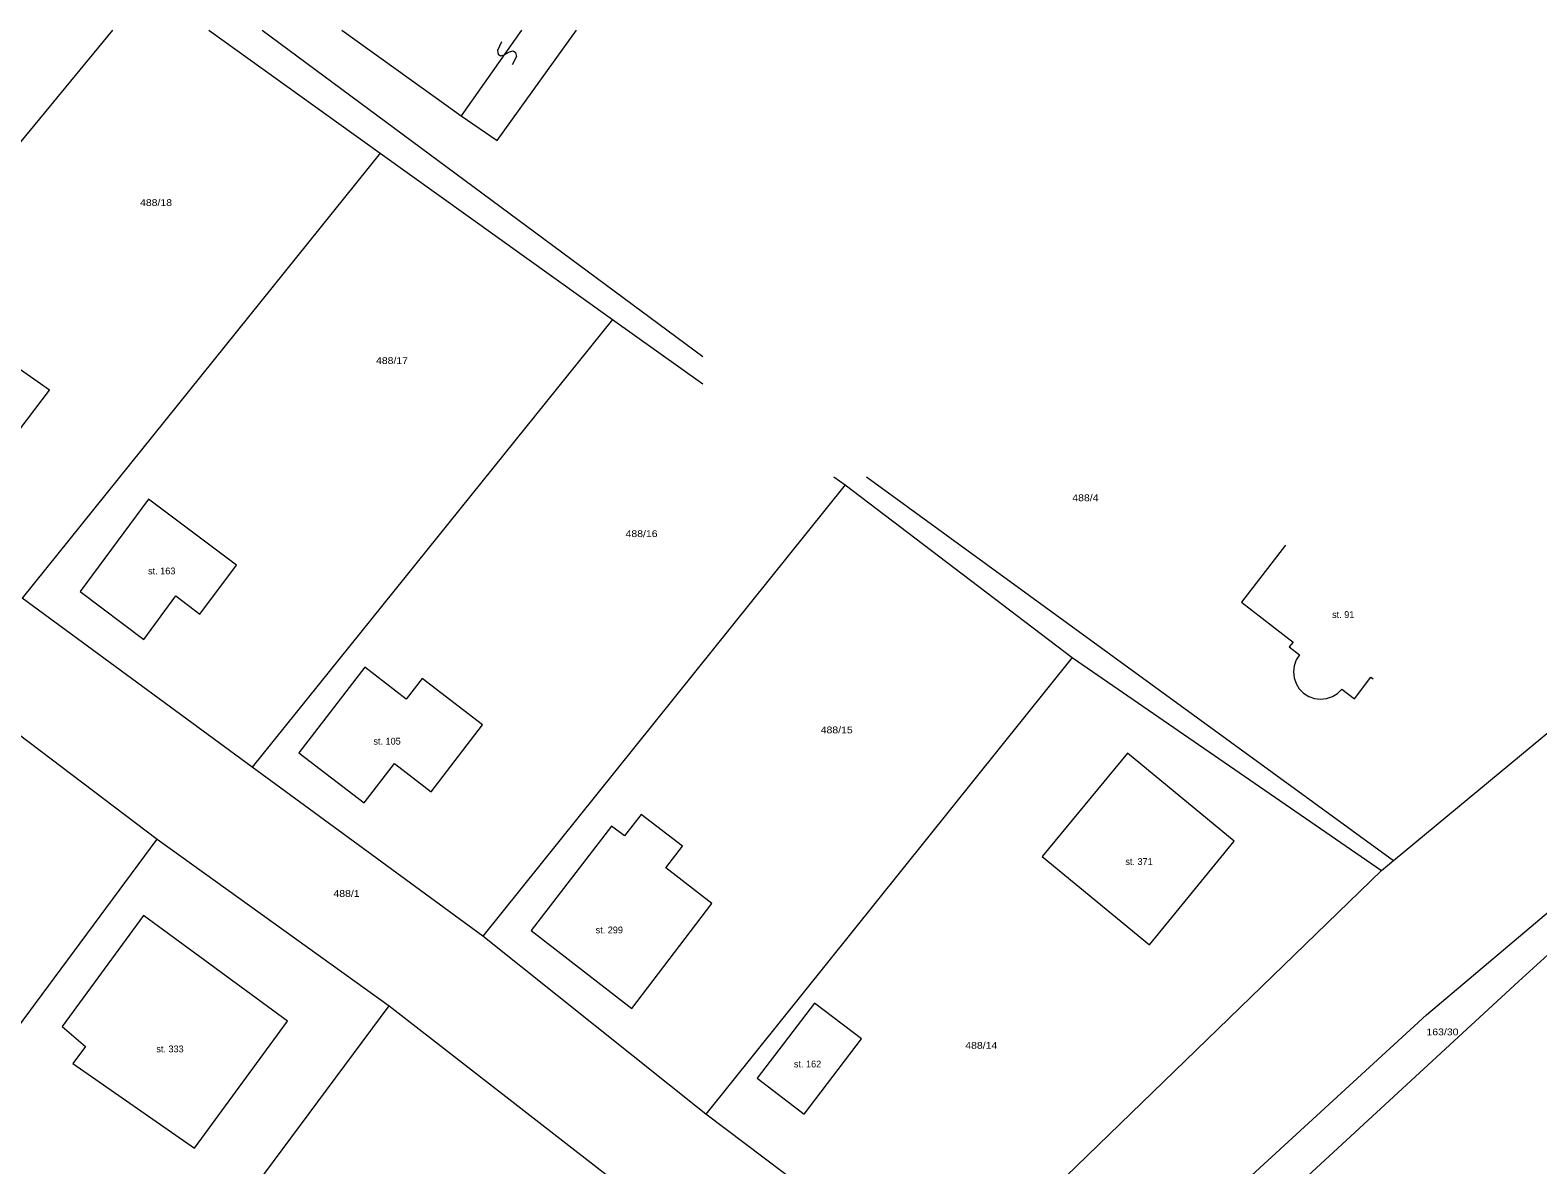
# Model space of a CAD drawing. Extents: x -694702 to -694000, y -1089746 to -1089192.
# Drawn here: x -694548.9 to -694438, y -1089489.2 to -1089405.7 of the extents above; entities that cross this region are included whole.
import ezdxf

# ---------------------------------------------------------------- set-up
doc = ezdxf.new("R2010")
doc.units = 0
doc.header["$LTSCALE"] = 0.2
doc.layers.add('50', color=7, linetype='Continuous', lineweight=13)
doc.layers.add('52', color=7, linetype='Continuous', lineweight=13)

msp = doc.modelspace()

# ---------------------------------------------------------------- linework, layer by layer
at = {"layer": '50'}
for p, q in [((-694542.8, -1089405.71), (-694566.61, -1089434.62)), ((-694535.71, -1089405.71), (-694523.11, -1089414.76)), ((-694531.78, -1089405.71), (-694499.38, -1089429.72)), ((-694512.73, -1089405.71), (-694517.17, -1089412.02)), ((-694523.11, -1089414.76), (-694549.44, -1089447.48)), ((-694523.11, -1089414.76), (-694506.04, -1089426.99)), ((-694506.04, -1089426.99), (-694532.52, -1089459.92)), ((-694506.04, -1089426.99), (-694499.38, -1089431.72)), ((-694489.75, -1089438.56), (-694488.92, -1089439.15)), ((-694487.36, -1089438.56), (-694448.6, -1089466.77)), ((-694488.92, -1089439.15), (-694515.56, -1089472.33)), ((-694488.92, -1089439.15), (-694472.22, -1089451.84)), ((-694532.52, -1089459.92), (-694549.44, -1089447.48)), ((-694472.22, -1089451.84), (-694499.16, -1089485.42)), ((-694472.22, -1089451.84), (-694449.48, -1089467.5)), ((-694556.16, -1089452.62), (-694539.5, -1089465.2)), ((-694448.6, -1089466.77), (-694436.92, -1089457.1)), ((-694515.56, -1089472.33), (-694532.52, -1089459.92)), ((-694563.62, -1089497.74), (-694539.5, -1089465.2)), ((-694539.5, -1089465.2), (-694522.45, -1089477.46)), ((-694449.48, -1089467.5), (-694448.6, -1089466.77)), ((-694479.49, -1089496.59), (-694449.48, -1089467.5)), ((-694499.16, -1089485.42), (-694515.56, -1089472.33)), ((-694546.56, -1089509.88), (-694522.45, -1089477.46)), ((-694522.45, -1089477.46), (-694505.84, -1089490.39))]:
    msp.add_line(p, q, dxfattribs=at)
for points in [[(-694525.94, -1089405.71), (-694517.17, -1089412.02), (-694514.52, -1089413.82), (-694508.68, -1089405.71)], [(-694456.55, -1089443.59), (-694459.79, -1089447.77), (-694455.99, -1089450.71), (-694456.27, -1089451.07), (-694455.52, -1089451.65)], [(-694455.52, -1089451.65), (-694455.76, -1089452.028), (-694455.911, -1089452.45), (-694455.964, -1089452.894), (-694455.918, -1089453.34), (-694455.773, -1089453.763), (-694455.538, -1089454.145), (-694455.529, -1089454.156), (-694455.213, -1089454.474), (-694454.835, -1089454.713), (-694454.413, -1089454.862), (-694453.968, -1089454.914), (-694453.523, -1089454.866), (-694453.099, -1089454.721), (-694452.719, -1089454.485), (-694452.4, -1089454.17)], [(-694452.4, -1089454.17), (-694451.47, -1089454.89), (-694450.26, -1089453.3), (-694450.1, -1089453.42)], [(-694473.4, -1089503.12), (-694446.18, -1089478.12), (-694429.84, -1089464.32)], [(-694471.06, -1089504.87), (-694439.41, -1089475.66), (-694429.16, -1089466.35)], [(-694479.49, -1089496.59), (-694484.8, -1089496.27), (-694499.16, -1089485.42)]]:
    msp.add_lwpolyline(points, dxfattribs=at)
for points in [[(-694552.18, -1089435.48), (-694550.74, -1089436.56), (-694547.43, -1089432.18), (-694556.26, -1089426.01), (-694562.37, -1089434.01), (-694555.14, -1089439.45)], [(-694536.37, -1089448.65), (-694533.67, -1089445.05), (-694540.15, -1089440.19), (-694545.17, -1089446.99), (-694540.5, -1089450.51), (-694538.14, -1089447.32)], [(-694520.03, -1089453.39), (-694521.19, -1089454.9), (-694524.24, -1089452.55), (-694529.09, -1089458.85), (-694524.29, -1089462.54), (-694522.07, -1089459.65), (-694519.37, -1089461.72), (-694515.59, -1089456.8)], [(-694468.16, -1089458.88), (-694474.44, -1089466.47), (-694466.54, -1089472.97), (-694460.32, -1089465.36)], [(-694498.73, -1089469.93), (-694502.1, -1089467.32), (-694500.88, -1089465.73), (-694503.93, -1089463.39), (-694505.15, -1089464.97), (-694506.1, -1089464.24), (-694512, -1089471.92), (-694504.6, -1089477.65)], [(-694529.92, -1089478.6), (-694540.52, -1089470.82), (-694546.49, -1089478.97), (-694544.78, -1089480.44), (-694545.71, -1089481.71), (-694536.77, -1089487.92)], [(-694491.93, -1089485.42), (-694487.72, -1089479.89), (-694491.18, -1089477.26), (-694495.39, -1089482.79)]]:
    msp.add_lwpolyline(points, close=True, dxfattribs=at)
at = {"layer": '52'}
msp.add_lwpolyline([(-694514.19, -1089406.56), (-694514.49, -1089407.2), (-694514.44, -1089407.48), (-694514.27, -1089407.59), (-694514, -1089407.53), (-694513.61, -1089407.3), (-694513.34, -1089407.24), (-694513.17, -1089407.35), (-694513.1, -1089407.64), (-694513.41, -1089408.27)], dxfattribs=at)

# ---------------------------------------------------------------- texts
at = {"layer": '52', "width": 1.15}
for s, p in [('488/18', (-694540.77, -1089418.64)), ('488/17', (-694523.42, -1089430.26)), ('488/4', (-694472.22, -1089440.35)), ('488/16', (-694505.07, -1089442.99)), ('488/15', (-694490.72, -1089457.42)), ('488/1', (-694526.55, -1089469.45)), ('163/30', (-694446.18, -1089479.63)), ('488/14', (-694480.09, -1089480.62))]:
    msp.add_text(s, height=0.5, dxfattribs=at).set_placement(p)
at = {"layer": '52'}
for s, p in [('st. 163', (-694540.18, -1089445.73)), ('st. 91', (-694453.12, -1089448.94)), ('st. 105', (-694523.61, -1089458.25)), ('st. 371', (-694468.32, -1089467.1)), ('st. 299', (-694507.27, -1089472.13)), ('st. 333', (-694539.57, -1089480.88)), ('st. 162', (-694492.69, -1089481.99))]:
    msp.add_text(s, height=0.5, dxfattribs=at).set_placement(p)

doc.saveas('drawing.dxf')
